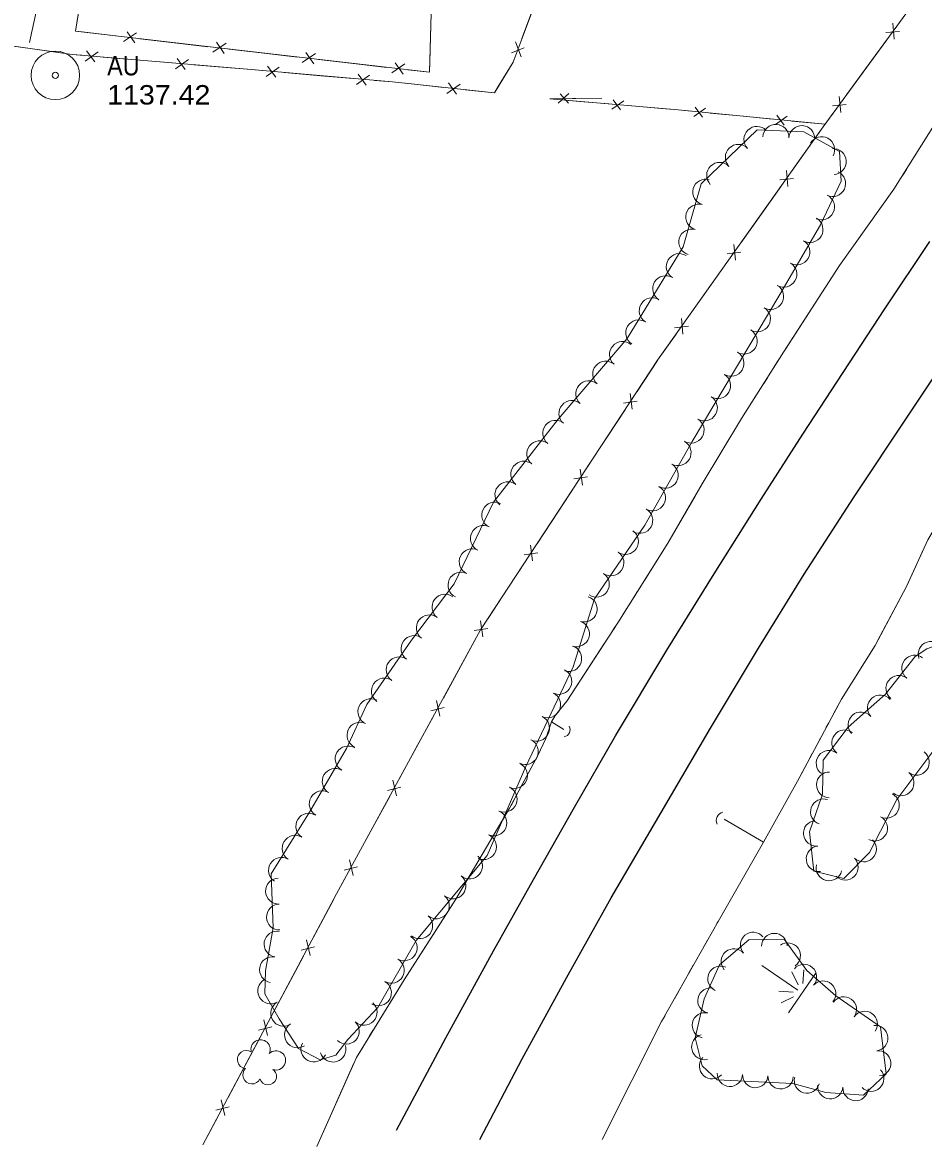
# Model space of a CAD drawing. Extents: x 296677 to 299172, y 46050 to 48373.
# Drawn here: x 297878.3 to 298156.8, y 46907.2 to 47254.7 of the extents above; entities that cross this region are included whole.
import ezdxf

# ---------------------------------------------------------------- set-up
doc = ezdxf.new("R2010")
doc.units = 0
doc.header["$LTSCALE"] = 2.4
doc.linetypes.add('LONG_DASHED', pattern=[7.5, 6, -1.5])
for name, color, linetype, lineweight in [('11', 7, 'Continuous', 25), ('15', 7, 'Continuous', 13), ('17', 7, 'LONG_DASHED', 13), ('18', 7, 'Continuous', 13), ('19', 7, 'Continuous', 13), ('6', 7, 'Continuous', 13)]:
    doc.layers.add(name, color=color, linetype=linetype, lineweight=lineweight)

msp = doc.modelspace()

# ---------------------------------------------------------------- linework, layer by layer
at = {"layer": '11'}
for points in [[(298019.649, 46909.369), (298032.706, 46934.301), (298046.486, 46959.382), (298060.266, 46984.166), (298075.743, 47010.457), (298090.987, 47036.558), (298105.83, 47061.356), (298119.928, 47084.202), (298135.395, 47108.043), (298152.172, 47133.361), (298169.529, 47159.369), (298189.917, 47189.118), (298209.655, 47217.416), (298226.429, 47241.723), (298245.674, 47268.289), (298265.185, 47295.988), (298285.166, 47324.097), (298307.161, 47354.894), (298328.486, 47384.422), (298348.071, 47411.701), (298368.67, 47440.188), (298389.533, 47469.344), (298407.334, 47494.128)], [(297993.929, 46912.343), (298009.102, 46940.862), (298023.823, 46967.759), (298036.203, 46989.741), (298048.938, 47012.197), (298061.6, 47034.179), (298077.442, 47060.686), (298092.121, 47084.325), (298106.655, 47107.326), (298119.525, 47127.448), (298131.934, 47146.556), (298144.819, 47166.218), (298158.695, 47187.074)]]:
    msp.add_lwpolyline(points, dxfattribs=at)
at = {"layer": '15'}
for p, q in [((298032.667, 47249.806), (298036.662, 47260.493)), ((298004.466, 47253.887), (298004.15, 47242.587)), ((298147.707, 47249.548), (298147.278, 47254.493)), ((297907.992, 47250.499), (297896.765, 47251.818)), ((297913.571, 47251.592), (297909.508, 47248.813)), ((297913.025, 47248.399), (297910.622, 47251.87)), ((298145.173, 47251.608), (298149.411, 47252.001)), ((297875.366, 47247.459), (297886.661, 47245.844)), ((297924.393, 47248.572), (297914.519, 47249.732)), ((297935.62, 47247.253), (297924.393, 47248.572)), ((297941.197, 47248.35), (297937.139, 47245.563)), ((297940.657, 47245.157), (297938.247, 47248.623)), ((298029.398, 47245.378), (298033.378, 47246.898)), ((298032.395, 47244.074), (298030.649, 47248.726)), ((298139.697, 47241.537), (298145.604, 47249.636)), ((297897.631, 47242.754), (297901.638, 47245.692)), ((297898.076, 47245.992), (297900.616, 47242.571)), ((297903.223, 47244.042), (297914.592, 47243.084)), ((297925.609, 47240.398), (297929.615, 47243.336)), ((297926.053, 47243.636), (297928.593, 47240.215)), ((297952.025, 47245.35), (297942.148, 47246.492)), ((297963.254, 47244.051), (297952.025, 47245.35)), ((297968.832, 47245.154), (297964.773, 47242.368)), ((297968.292, 47241.961), (297965.882, 47245.427)), ((297979.659, 47242.154), (297969.783, 47243.296)), ((297914.592, 47243.084), (297924.591, 47242.242)), ((297931.201, 47241.685), (297942.569, 47240.728)), ((297953.578, 47238.019), (297957.594, 47240.945)), ((297954.033, 47241.256), (297956.562, 47237.827)), ((297990.889, 47240.855), (297979.659, 47242.154)), ((297996.466, 47241.958), (297992.408, 47239.172)), ((297995.926, 47238.765), (297993.517, 47242.231)), ((298132.981, 47232.329), (298139.697, 47241.537)), ((297959.174, 47239.289), (297970.54, 47238.296)), ((297970.54, 47238.296), (297980.536, 47237.422)), ((297981.548, 47235.574), (297985.564, 47238.5)), ((297982.003, 47238.811), (297984.532, 47235.382)), ((297998.499, 47235.738), (298008.476, 47234.673)), ((298009.453, 47232.806), (298013.524, 47235.655)), ((298009.969, 47236.034), (298012.432, 47232.557)), ((298047.196, 47232.799), (298043.835, 47229.816)), ((298047.068, 47229.845), (298044.494, 47232.712)), ((298057.342, 47231.305), (298048.268, 47231.223)), ((298050.524, 47230.353), (298059.564, 47229.566)), ((298060.48, 47227.895), (298064.111, 47230.542)), ((298060.89, 47230.822), (298063.178, 47227.722)), ((298128.645, 47228.947), (298132.883, 47229.34)), ((298131.179, 47226.887), (298130.75, 47231.832)), ((298065.54, 47229.045), (298075.819, 47228.15)), ((298085.754, 47225.641), (298089.413, 47228.249)), ((298086.196, 47228.564), (298088.45, 47225.439)), ((298090.826, 47226.737), (298101.095, 47225.732)), ((298111.466, 47226.091), (298113.721, 47222.967)), ((298101.095, 47225.732), (298110.127, 47224.849)), ((298111.025, 47223.168), (298114.684, 47225.777)), ((298116.097, 47224.265), (298126.366, 47223.26)), ((298116.62, 47209.548), (298123.216, 47218.843)), ((298114.889, 47204.083), (298114.395, 47209.022)), ((298112.329, 47206.11), (298116.561, 47206.558)), ((298106.984, 47195.969), (298112.785, 47204.144)), ((298100.388, 47186.674), (298106.984, 47195.969)), ((298098.657, 47181.209), (298098.163, 47186.148)), ((298090.752, 47173.095), (298096.553, 47181.27)), ((298096.097, 47183.236), (298100.329, 47183.684)), ((298084.156, 47163.8), (298090.752, 47173.095)), ((298079.865, 47160.362), (298084.097, 47160.81)), ((298082.425, 47158.335), (298081.931, 47163.274)), ((298068.27, 47140.69), (298074.525, 47150.218)), ((298066.737, 47135.167), (298066.065, 47140.084)), ((298064.106, 47137.099), (298068.319, 47137.7)), ((298059.131, 47126.772), (298064.633, 47135.151)), ((298052.876, 47117.244), (298059.131, 47126.772)), ((298051.344, 47111.72), (298050.672, 47116.638)), ((298043.738, 47103.325), (298049.24, 47111.705)), ((298048.712, 47113.653), (298052.926, 47114.254)), ((298037.483, 47093.798), (298043.738, 47103.325)), ((298033.319, 47090.206), (298037.532, 47090.807)), ((298035.951, 47088.274), (298035.278, 47093.192)), ((298028.345, 47079.879), (298033.846, 47088.258)), ((298022.089, 47070.351), (298028.345, 47079.879)), ((298020.557, 47064.827), (298019.885, 47069.745)), ((298017.925, 47066.76), (298022.139, 47067.361)), ((298013.835, 47055.903), (298018.633, 47064.704)), ((298008.379, 47045.896), (298013.835, 47055.903)), ((298004.523, 47041.976), (298008.673, 47042.92)), ((298007.304, 47040.265), (298006.232, 47045.111)), ((298000.41, 47031.276), (298005.208, 47040.078)), ((297994.954, 47021.269), (298000.41, 47031.276)), ((297991.098, 47017.35), (297995.248, 47018.293)), ((297993.879, 47015.639), (297992.807, 47020.485)), ((297986.984, 47006.65), (297991.783, 47015.451)), ((297981.529, 46996.643), (297986.984, 47006.65)), ((297977.672, 46992.723), (297981.823, 46993.667)), ((297980.454, 46991.012), (297979.382, 46995.859)), ((297968.235, 46971.946), (297973.592, 46982.006)), ((297964.417, 46967.989), (297968.558, 46968.973)), ((297967.215, 46966.305), (297966.095, 46971.141)), ((297960.409, 46957.249), (297965.121, 46966.097)), ((297955.052, 46947.189), (297960.409, 46957.249)), ((297954.032, 46941.548), (297952.913, 46946.384)), ((297947.227, 46932.492), (297951.938, 46941.34)), ((297951.234, 46943.232), (297955.375, 46944.216)), ((297941.87, 46922.432), (297947.227, 46932.492)), ((297940.85, 46916.791), (297939.73, 46921.627)), ((297934.044, 46907.735), (297938.755, 46916.583)), ((297938.052, 46918.475), (297942.193, 46919.459))]:
    msp.add_line(p, q, dxfattribs=at)
for points in [[(297934.044, 46907.735), (297975.364, 46985.334), (298019.861, 47066.957), (298074.609, 47150.346), (298125.783, 47222.46), (298178.264, 47294.414), (298225.978, 47358.72), (298274.598, 47426.93), (298317.324, 47484.772), (298356.323, 47534.793)], [(297997.669, 47320.362), (298006.322, 47316.56), (298005.181, 47279.429), (298004.059, 47239.332), (297939.008, 47246.855), (297894.644, 47252.067), (297904.424, 47311.835), (297906.791, 47320.577), (297946.268, 47322.423)], [(297779.778, 46909.61), (297794.554, 46946.422), (297807.458, 46977.755), (297817.225, 47048.875), (297822.114, 47083.236), (297825.595, 47107.902), (297829.355, 47122.614), (297848.322, 47177.352), (297873.74, 47242.748), (297874.944, 47247.519), (297893.603, 47244.852), (297946.629, 47240.386), (297992.624, 47236.365), (298024.19, 47232.996), (298029.924, 47242.469), (298041.045, 47272.217)], [(297896.765, 47251.818), (297894.644, 47252.067), (297895.905, 47259.772)], [(297886.661, 47245.844), (297893.603, 47244.852), (297896.614, 47244.598)], [(298025.349, 47234.911), (298029.924, 47242.469), (298030.344, 47243.593)], [(297942.569, 47240.728), (297946.629, 47240.386), (297952.566, 47239.867)], [(298004.15, 47242.587), (298004.059, 47239.332), (297997.417, 47240.1)], [(297987.144, 47236.844), (297992.624, 47236.365), (297998.499, 47235.738)], [(298015.072, 47233.969), (298024.19, 47232.996), (298025.349, 47234.911)], [(298057.342, 47231.305), (298041.255, 47231.16), (298080.92, 47227.706), (298126.366, 47223.26)], [(298042.269, 47231.169), (298041.255, 47231.16), (298050.524, 47230.353)], [(298075.819, 47228.15), (298080.92, 47227.706), (298084.856, 47227.321)], [(298123.216, 47218.843), (298125.783, 47222.46), (298129.076, 47226.975)], [(298074.525, 47150.218), (298074.609, 47150.346), (298080.322, 47158.396)], [(297973.592, 46982.006), (297975.364, 46985.334), (297978.357, 46990.825)]]:
    msp.add_lwpolyline(points, dxfattribs=at)
for centre, radius, start, end in [((298045.283, 47036.14), 2.281, 281.83123, 28.0708), ((298095.253, 47008.056), 2.562, 100.53318, 206.77274)]:
    msp.add_arc(centre, radius, start, end, dxfattribs=at)
at = {"layer": '17'}
msp.add_lwpolyline([(297891.674, 47351.263), (297890.09, 47321.056), (297887.452, 47290.551), (297884.069, 47269.097), (297882.611, 47258.516), (297880.507, 47248.524)], dxfattribs=at)
at = {"layer": '18'}
for points in [[(297988.134, 46950.243), (297999.971, 46970.906), (298021.89, 46997.221), (298033.841, 47024.705), (298048.544, 47055.584), (298055.099, 47076.531), (298070.686, 47099.377), (298085.284, 47125.171), (298098.686, 47147.618), (298112.381, 47170.684), (298124.967, 47192.133), (298131.358, 47205.676), (298130.772, 47214.806), (298119.79, 47220.908), (298105.383, 47221.604), (298088.017, 47204.846), (298082.542, 47185.346), (298065.198, 47157.017), (298043.843, 47132.121), (298023.834, 47106.406), (298011.7, 47081.222), (297998.537, 47063.747), (297984.716, 47043.919), (297978.392, 47030.26), (297967.003, 47010.577), (297955.175, 46991.502), (297955.739, 46974.841), (297953.386, 46961.602), (297953.164, 46954.413), (297957.631, 46946.662), (297963.554, 46937.506), (297970.323, 46934.015), (297975.128, 46935.428), (297978.805, 46940.28)], [(298145.059, 47047.042), (298133.48, 47036.867), (298125.769, 47026.731), (298125.546, 47016.185), (298121.509, 47004.568), (298122.847, 46992.381), (298132.119, 46990.145), (298140.12, 46998.13), (298148.588, 47014.469), (298162.745, 47033.494), (298167.652, 47048.195), (298167.481, 47058.516), (298163.008, 47062.91), (298157.77, 47061.15), (298154.231, 47058.746)], [(298116.436, 46926.695), (298126.561, 46923.917), (298138.229, 46923.095), (298145.215, 46929.741), (298143.526, 46944.267), (298129.734, 46953.781), (298120.679, 46961.643), (298113.728, 46971.331), (298102.811, 46971.131), (298093.73, 46963.356), (298088.965, 46952.919), (298086.229, 46940.819), (298088.37, 46932.139), (298092.987, 46927.863)]]:
    msp.add_lwpolyline(points, close=True, dxfattribs=at)
for centre, radius, start, end in [((298105.303, 47218.612), 4.007, 43.98691, 223.97159), ((298111.154, 47219.225), 4.007, 357.24186, 177.22654), ((298119.158, 47218.839), 4.007, 357.24186, 177.22654), ((298125.311, 47215.441), 4.007, 330.94951, 150.93419), ((298099.537, 47213.048), 4.007, 43.98691, 223.97159), ((298128.867, 47211.746), 4.007, 273.6801, 93.66478), ((298093.77, 47207.483), 4.007, 43.98691, 223.97159), ((298128.695, 47204.946), 4.007, 244.74484, 64.72951), ((298089.484, 47202.313), 4.007, 74.32455, 254.30923), ((298087.318, 47194.598), 4.007, 74.32455, 254.30923), ((298125.275, 47197.699), 4.007, 244.74484, 64.72951), ((298121.717, 47190.738), 4.007, 239.60379, 59.58847), ((298085.152, 47186.883), 4.007, 74.32455, 254.30923), ((298117.661, 47183.826), 4.007, 239.60379, 59.58847), ((298081.287, 47179.28), 4.007, 58.53124, 238.51592), ((298113.606, 47176.915), 4.007, 239.60379, 59.58847), ((298077.103, 47172.446), 4.007, 58.53124, 238.51592), ((298109.547, 47170.018), 4.007, 239.30874, 59.29342), ((298072.919, 47165.611), 4.007, 58.53124, 238.51592), ((298105.455, 47163.128), 4.007, 239.30874, 59.29342), ((298068.735, 47158.777), 4.007, 58.53124, 238.51592), ((298101.364, 47156.237), 4.007, 239.30874, 59.29342), ((298063.752, 47152.11), 4.007, 49.38571, 229.37039), ((298058.535, 47146.028), 4.007, 49.38571, 229.37039), ((298097.273, 47149.347), 4.007, 239.30874, 59.29342), ((298053.318, 47139.945), 4.007, 49.38571, 229.37039), ((298093.17, 47142.47), 4.007, 239.16831, 59.15299), ((298089.062, 47135.589), 4.007, 239.16831, 59.15299), ((298048.1, 47133.863), 4.007, 49.38571, 229.37039), ((298084.954, 47128.709), 4.007, 239.16831, 59.15299), ((298043.091, 47127.74), 4.007, 52.12096, 232.10563), ((298038.17, 47121.415), 4.007, 52.12096, 232.10563), ((298080.925, 47121.726), 4.007, 240.50016, 60.48484), ((298033.249, 47115.091), 4.007, 52.12096, 232.10563), ((298076.978, 47114.752), 4.007, 240.50016, 60.48484), ((298028.328, 47108.766), 4.007, 52.12096, 232.10563), ((298073.031, 47107.778), 4.007, 240.50016, 60.48484), ((298024.252, 47102.441), 4.007, 64.28225, 244.26693), ((298069.084, 47100.804), 4.007, 240.50016, 60.48484), ((298020.773, 47095.222), 4.007, 64.28225, 244.26693), ((298064.692, 47094.313), 4.007, 235.70336, 55.68803), ((298017.295, 47088.002), 4.007, 64.28225, 244.26693), ((298060.176, 47087.694), 4.007, 235.70336, 55.68803), ((298013.817, 47080.783), 4.007, 64.28225, 244.26693), ((298055.66, 47081.074), 4.007, 235.70336, 55.68803), ((298008.869, 47073.977), 4.007, 53.01887, 233.00354), ((298051.919, 47073.393), 4.007, 252.63106, 72.61573), ((298004.047, 47067.577), 4.007, 53.01887, 233.00354), ((298049.526, 47065.745), 4.007, 252.63106, 72.61573), ((297999.32, 47061.203), 4.007, 55.12944, 235.11412), ((298159.135, 47059.412), 3.978, 18.58032, 198.565), ((298047.133, 47058.097), 4.007, 252.63106, 72.61573), ((298154.058, 47055.15), 3.978, 51.92315, 231.90783), ((297994.738, 47054.629), 4.007, 55.12944, 235.11412), ((298044.055, 47051.036), 4.007, 244.54626, 64.53094), ((298149.151, 47048.888), 3.978, 51.92315, 231.90783), ((297990.156, 47048.055), 4.007, 55.12944, 235.11412), ((297985.985, 47041.668), 4.007, 65.16393, 245.14861), ((298040.61, 47043.801), 4.007, 244.54626, 64.53094), ((298143.445, 47042.852), 3.978, 41.31492, 221.2996), ((297982.618, 47034.396), 4.007, 65.16393, 245.14861), ((298037.165, 47036.565), 4.007, 244.54626, 64.53094), ((298137.469, 47037.6), 3.978, 41.31492, 221.2996), ((298132.428, 47032.045), 3.978, 52.74546, 232.73014), ((298033.72, 47029.33), 4.007, 244.54626, 64.53094), ((297978.963, 47027.059), 4.007, 59.95308, 239.93776), ((298127.611, 47025.713), 3.978, 52.74546, 232.73014), ((298154.592, 47026.026), 3.978, 233.35376, 53.33844), ((298030.367, 47021.975), 4.007, 246.50658, 66.49126), ((297974.949, 47020.123), 4.007, 59.95308, 239.93776), ((298127.689, 47019.038), 3.978, 88.7963, 268.78098), ((298149.843, 47019.644), 3.978, 233.35376, 53.33844), ((298027.171, 47014.626), 4.007, 246.50658, 66.49126), ((297970.936, 47013.187), 4.007, 59.95308, 239.93776), ((298125.852, 47010.723), 3.978, 70.84491, 250.82959), ((298145.334, 47012.715), 3.978, 242.61135, 62.59602), ((298023.976, 47007.277), 4.007, 246.50658, 66.49126), ((297966.791, 47006.255), 4.007, 58.20549, 238.19017), ((298123.657, 47004.084), 3.978, 96.27302, 276.2577), ((298141.673, 47005.651), 3.978, 242.61135, 62.59602), ((298020.78, 46999.928), 4.007, 246.50658, 66.49126), ((297962.568, 46999.445), 4.007, 58.20549, 238.19017), ((298124.525, 46996.176), 3.978, 96.27302, 276.2577), ((298138.25, 46999.206), 3.978, 224.95032, 44.93499), ((297958.345, 46992.634), 4.007, 58.20549, 238.19017), ((298016.456, 46993.974), 4.007, 230.21516, 50.19983), ((298127.58, 46993.381), 3.978, 166.44931, 346.43399), ((298132.619, 46993.586), 3.978, 224.95032, 44.93499), ((297957.453, 46986.195), 4.007, 91.94647, 271.93115), ((298011.327, 46987.816), 4.007, 230.21516, 50.19983), ((298006.198, 46981.659), 4.007, 230.21516, 50.19983), ((297957.724, 46978.186), 4.007, 91.94647, 271.93115), ((298001.069, 46975.502), 4.007, 230.21516, 50.19983), ((297956.975, 46969.81), 4.007, 79.92958, 259.91426), ((298104.135, 46969.562), 3.923, 40.57724, 220.56192), ((298110.678, 46969.221), 3.923, 1.05721, 181.04188), ((297996.273, 46968.669), 4.007, 240.20101, 60.18568), ((298114.833, 46966.269), 3.923, 305.66656, 125.65123), ((297955.573, 46961.92), 4.007, 79.92958, 259.91426), ((298098.176, 46964.459), 3.923, 40.57724, 220.56192), ((297992.289, 46961.716), 4.007, 240.20101, 60.18568), ((298094.04, 46959.091), 3.923, 65.46865, 245.45333), ((298119.845, 46959.648), 3.923, 319.04153, 139.02621), ((297955.044, 46955.352), 4.007, 119.96306, 299.94773), ((298125.769, 46954.504), 3.923, 319.04153, 139.02621), ((297988.306, 46954.763), 4.007, 240.20101, 60.18568), ((298090.941, 46952.346), 3.923, 77.26645, 257.25113), ((297959.045, 46948.409), 4.007, 119.96306, 299.94773), ((297983.865, 46948.752), 4.007, 226.88992, 46.87459), ((298132.171, 46949.605), 3.923, 325.40897, 145.39364), ((298089.21, 46944.694), 3.923, 77.26645, 257.25113), ((298138.629, 46945.151), 3.923, 325.40897, 145.39364), ((297963.306, 46941.751), 4.007, 122.90642, 302.89109), ((297978.388, 46942.903), 4.007, 226.88992, 46.87459), ((298141.869, 46940.739), 3.923, 276.63991, 96.62458), ((298089.039, 46938.002), 3.923, 103.8636, 283.84828), ((297951.887, 46937.25), 2.974, 334.0166, 195.25048), ((297968.35, 46937.392), 4.007, 152.72599, 332.71067), ((297974.252, 46937.356), 4.007, 196.39462, 16.3793), ((297947.505, 46934.139), 2.777, 56.98749, 264.76048), ((297956.654, 46933.851), 2.975, 251.66742, 134.64069), ((298091.462, 46932.074), 3.923, 137.20358, 317.18826), ((298142.775, 46932.947), 3.923, 276.63991, 96.62458), ((297949.173, 46929.36), 2.783, 133.66451, 334.67555), ((297954.194, 46928.906), 2.611, 196.37265, 54.30526), ((298140.627, 46928.21), 3.923, 223.57892, 43.5636), ((298096.95, 46929.721), 3.923, 177.1561, 357.14078), ((298104.785, 46929.331), 3.923, 177.1561, 357.14078), ((298112.621, 46928.941), 3.923, 177.1561, 357.14078), ((298120.763, 46927.637), 3.923, 164.66496, 344.64963), ((298127.971, 46925.876), 3.923, 175.97788, 355.96256), ((298135.797, 46925.325), 3.923, 175.97788, 355.96256)]:
    msp.add_arc(centre, radius, start, end, dxfattribs=at)
at = {"layer": '19'}
for p, q in [((298153.719, 47212.857), (298154.834, 47214.628)), ((298150.376, 47207.542), (298151.491, 47209.314)), ((298114.122, 47153.75), (298130.559, 47179.267)), ((298110.759, 47148.447), (298111.877, 47150.217)), ((298107.405, 47143.139), (298108.523, 47144.909)), ((298104.05, 47137.832), (298105.168, 47139.601)), ((298155.856, 47089.886), (298156.6, 47091.51)), ((298067.213, 47076.964), (298068.328, 47078.734)), ((298063.868, 47071.653), (298064.983, 47073.423)), ((298060.483, 47066.368), (298061.624, 47068.122)), ((298126.641, 47036.637), (298127.486, 47038.214)), ((298124.105, 47031.907), (298124.95, 47033.484)), ((298121.569, 47027.176), (298122.414, 47028.753)), ((298029.312, 47012.678), (298030.229, 47014.393)), ((298026.38, 47007.635), (298027.369, 47009.309)), ((298023.413, 47002.611), (298024.402, 47004.286)), ((298088.543, 46968.429), (298090, 46971.013)), ((298084.172, 46960.677), (298085.629, 46963.261)), ((298106.821, 46963.187), (298117.893, 46955.604)), ((298119.817, 46961.819), (298119.459, 46957.598)), ((298115.059, 46948.546), (298123.419, 46960.752)), ((298118.066, 46957.219), (298116.133, 46961.21)), ((298079.802, 46952.926), (298081.258, 46955.51)), ((298116.481, 46954.905), (298112.061, 46955.265)), ((298112.824, 46951.61), (298116.631, 46953.469)), ((297988.643, 46946.38), (297989.661, 46948.037)), ((297985.588, 46941.411), (297986.606, 46943.068)), ((297982.533, 46936.442), (297983.551, 46938.099)), ((297969.251, 46907.237), (297980.725, 46933.008))]:
    msp.add_line(p, q, dxfattribs=at)
for points in [[(298107.322, 47001.324), (298117.849, 47020.236), (298131.431, 47045.573), (298141.828, 47062.14), (298151.503, 47080.373), (298158.084, 47094.754), (298166.888, 47109.501), (298181.763, 47130.176), (298193.198, 47148.329), (298207.14, 47170.844), (298218.166, 47189.253), (298229.804, 47206.087), (298241.266, 47221.699), (298250.81, 47234.929), (298255.094, 47242.343), (298256.656, 47244.904)], [(298041.763, 47038.532), (298042.964, 47040.495), (298046.509, 47044.878), (298062.28, 47069.131), (298077.807, 47093.786), (298088.377, 47112.101), (298100.554, 47132.299), (298113.514, 47152.807), (298130.779, 47179.609), (298147.625, 47203.168), (298160.73, 47224.002)], [(298130.559, 47179.267), (298130.779, 47179.609), (298147.625, 47203.168), (298148.148, 47203.999)], [(298086.174, 47108.284), (298088.377, 47112.101), (298100.554, 47132.299), (298101.814, 47134.293)], [(298070.557, 47082.274), (298077.807, 47093.786), (298086.174, 47108.284)], [(298142.58, 47063.558), (298151.503, 47080.373), (298154.369, 47086.637)], [(298041.763, 47038.532), (298042.964, 47040.495), (298046.509, 47044.878), (298058.202, 47062.86)], [(298129.177, 47041.368), (298131.431, 47045.573), (298141.828, 47062.14), (298142.58, 47063.558)], [(297969.251, 46907.237), (297981.52, 46934.795), (297996.272, 46958.789), (298012.243, 46983.698), (298028.866, 47011.843), (298037.556, 47028.102), (298040.044, 47033.374), (298041.763, 47038.532), (298045.616, 47036.131)], [(298032.062, 47017.823), (298037.556, 47028.102), (298040.044, 47033.374), (298041.763, 47038.532), (298045.616, 47036.131)], [(298107.322, 47001.324), (298117.849, 47020.236), (298119.878, 47024.022)], [(298057.459, 46909.387), (298075.824, 46945.872), (298093.271, 46976.814), (298107.322, 47001.324), (298095.211, 47008.406)], [(298092.914, 46976.18), (298093.271, 46976.814), (298107.322, 47001.324), (298095.211, 47008.406)], [(298006.778, 46975.175), (298012.243, 46983.698), (298021.435, 46999.262)], [(297991.698, 46951.349), (297996.272, 46958.789), (298006.778, 46975.175)], [(298057.459, 46909.387), (298075.824, 46945.872), (298076.888, 46947.759)]]:
    msp.add_lwpolyline(points, dxfattribs=at)
at = {"layer": '6'}
for radius in [7.5, 0.96]:
    msp.add_circle((297888.463, 47238.384), radius, dxfattribs=at)

# ---------------------------------------------------------------- texts
for s, width, p in [('AU', 0.9, (297904.463, 47238.384)), ('1137.42', 1.1, (297904.463, 47229.384))]:
    msp.add_text(s, height=6, dxfattribs=dict(at, width=width)).set_placement(p)

doc.saveas('drawing.dxf')
